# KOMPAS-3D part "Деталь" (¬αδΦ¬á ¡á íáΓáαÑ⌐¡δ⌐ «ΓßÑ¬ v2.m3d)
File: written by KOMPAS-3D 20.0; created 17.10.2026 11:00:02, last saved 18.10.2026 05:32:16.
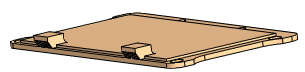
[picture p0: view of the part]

Document properties: Полное имя файла: D:\myProjects\Progect_esp32\box_compas\корпус\крышка на батарейный отсек v2.m3d

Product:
- Part/product: Деталь
    Масса: 0.0739347
  - Body: Тело 5
      Масса: 0.0737567
  - Body: Тело 2
      Масса: 0.0737567
  - Body: Тело 1
      Масса: 0.0737567

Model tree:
1. Эскиз:1
2. Элемент выдавливания:1
     Расстояние 1 = 0.8
3. Эскиз:2  (with: Элемент выдавливания:1)
4. Элемент выдавливания:2
     Расстояние 1 = 1.6
5. Эскиз:5  (with: Элемент выдавливания:2)
6. Элемент выдавливания:6
     Расстояние 2 = 1.6
7. Эскиз:6  (with: Элемент выдавливания:2, Элемент выдавливания:1)
8. Элемент выдавливания:7
     Расстояние 2 = 1
9. Массив по сетке:2  (with: Элемент выдавливания:7, Эскиз:6)  (4 pattern instances)
     Шаг 1 = 83.2; Угол раствора = -90; Шаг 2 = 36.8
10. Скругление:1  (with: Элемент выдавливания:2)
     Радиус = 4
11. Эскиз:8  (with: Элемент выдавливания:2)
12. Элемент выдавливания:8
     Расстояние 2 = 2.4
13. Смещенная плоскость:1  (with: Элемент выдавливания:2)
     Расстояние = -45
14. Зеркальный массив:1
15. Экземпляр ( 1 )
16. Экземпляр ( 2 )  (with: Элемент выдавливания:8)
17. Эскиз:10  (with: Элемент выдавливания:1)
18. Элемент выдавливания:9
     Расстояние 1 = 1.5
19. Эскиз:11  (with: Элемент выдавливания:9)
20. Элемент выдавливания:10
     Расстояние 1 = 1.5
21. Скругление:4  (with: Элемент выдавливания:10)
     Радиус = 1
22. Эскиз:15  (with: Элемент выдавливания:9, Элемент выдавливания:10, Скругление:4, Элемент выдавливания:1)
23. Эскиз:16  (with: Элемент выдавливания:9, Элемент выдавливания:10, Скругление:4, Элемент выдавливания:1)
24. Элемент выдавливания:13
     Расстояние 2 = 0.8
25. Скругление:6  (with: Элемент выдавливания:9)
     Радиус = 1
26. Элемент выдавливания:14
     Расстояние 2 = 0.8
27. Массив по сетке:5  (with: Элемент выдавливания:14, Элемент выдавливания:10)  (5 pattern instances)
     Шаг 1 = 1.6; Угол раствора = 90
28. Скругление:7  (with: Элемент выдавливания:9)
     Радиус = 1.2
29. Массив по сетке:6  (with: Элемент выдавливания:13, Элемент выдавливания:1)  (5 pattern instances)
     Шаг 1 = 1.6; Угол раствора = 90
